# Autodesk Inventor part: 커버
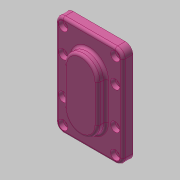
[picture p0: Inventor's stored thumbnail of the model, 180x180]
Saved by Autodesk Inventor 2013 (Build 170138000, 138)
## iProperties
Created: 2019-03
Part Number: 커버
Material: 알루미늄 6061
Document SubType Name: Modeling
Designer: mduedu
Density: 1 g/cm^3
Author: mduedu
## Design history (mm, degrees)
sketch "스케치1"
  geometry: L1 (-60, 40)-(60, 40); L2 (60, 40)-(60, -40); L3 (60, -40)-(-60, -40); L4 (-60, -40)-(-60, 40); L5 (-60, 40)-(60, -40); L6 (60, 40)-(-60, -40); 1 further point
  constraints: 12 end point, 2 midpoint, 2 parallel, 1 horizontal, 1 perpendicular
  dimensions: "d59" = 120 distance of L2.end L3.end; "d60" = 80 distance of L1.end L2.end
extrude "돌출1" new body sketch "스케치1" distance "d4" = 12; taper "d5" = 0 deg
sketch "스케치2"
  geometry: L1 (-20, -22)-(20, -22); L2 (20, -22)-(20, 22); L3 (20, 22)-(-20, 22); L4 (-20, 22)-(-20, -22); L5 (-20, -22)-(20, 22); L6 (20, -22)-(-20, 22); 3 further points
  constraints: 12 end point, 4 midpoint, 2 horizontal alignment, 2 parallel, 1 horizontal, 1 perpendicular, 4 other
  dimensions: "d6" = 40 distance between parallel lines of L2 L4; "d8" = 44 distance between parallel lines of L1 L3
extrude "돌출2" join sketch "스케치2" distance "d9" = 10; taper "d10" = 0 deg
fillet "모깎기1" dims "d11" = 9
fillet "모깎기2" dims "d12" = 3
sketch "스케치3"
  geometry: L1 (-31, -60)-(31, -60) reference; L2 (-40, 51)-(-40, -51) reference; L3 (31, 60)-(-31, 60) reference; L4 (40, -51)-(40, 51) reference; L5 (-17, -22)-(-17, 22) reference; L6 (17, 22)-(17, -22) reference; L7 (-31, 51)-(31, 51); L8 (31, 51)-(31, -51); L9 (31, -51)-(-31, -51); L10 (-31, -51)-(-31, 51); A1 r 9 centre (31, -51) between (31, -60) and (40, -51) reference; A2 r 9 centre (-31, -51) between (-40, -51) and (-31, -60) reference; A3 r 9 centre (-31, 51) between (-31, 60) and (-40, 51) reference; A4 r 9 centre (31, 51) between (40, 51) and (31, 60) reference; A5 r 17 centre (0, -22) between (-17, -22) and (17, -22) reference; A6 r 17 centre (0, 22) between (17, 22) and (-17, 22) reference; 9 further points
  constraints: 8 end point, 4 coincident, 4 horizontal alignment, 4 point on line, 2 parallel, 1 horizontal, 1 perpendicular
hole "구멍2" sketch "스케치3" at (-31, 51), (31, 51), (31, -51), (-31, -51), (-31, 22), (-31, -22), (31, 22), (31, -22) diameter "d28" = 5.5; stored, may be unused: countersink angle "d32" = 90 deg, drill point angle "d34" = 118 deg; dims "d29" = 6, "d30" = 4, "d31" = 2, "d33" = 8
sketch "스케치9"
  geometry: L1 (40, -51)-(40, 51) reference; L2 (31, 60)-(-31, 60) reference; L3 (-40, 51)-(-40, -51) reference; L4 (-31, -60)-(31, -60) reference; L5 (23, -22)-(23, 22) reference; L6 (-23, 22)-(-23, -22) reference; C1 r 2.75 at (31, 22) reference; C2 r 2.75 at (-31, 22) reference; C3 r 2.75 at (31, -51) reference; C4 r 2.75 at (-31, 51) reference; C5 r 2.75 at (31, 51) reference; C6 r 2.75 at (-31, -51) reference; C7 r 2.75 at (-31, -22) reference; C8 r 2.75 at (31, -22) reference; A1 r 9 centre (31, -51) between (31, -60) and (40, -51) reference; A2 r 9 centre (31, 51) between (40, 51) and (31, 60) reference; A3 r 9 centre (-31, 51) between (-31, 60) and (-40, 51) reference; A4 r 9 centre (-31, -51) between (-40, -51) and (-31, -60) reference; A5 r 23 centre (0, -22) between (-23, -22) and (23, -22) reference; A6 r 23 centre (0, 22) between (23, 22) and (-23, 22) reference; 9 further points
  constraints: 8 coincident
hole "구멍4" sketch "스케치9" at (-31, 51), (31, 51), (31, 22), (-31, 22), (-31, -22), (31, -22), (31, -51), (-31, -51) diameter "d69" = 11; stored, may be unused: countersink angle "d73" = 90 deg, drill point angle "d75" = 0 deg; dims "d70" = 6, "d71" = 4, "d72" = 2, "d74" = 5.4
fillet "모깎기3" dims "d68" = 3
sketch "스케치6"
  geometry: C1 r 12.5 at (0, 22); 1 further point
  constraints: 1 centre point, 1 vertical alignment
  dimensions: "d43" = 25 diameter of C1; "d45" = 22 distance of C1.centre point (0, 0)
extrude "돌출5" cut sketch "스케치6" distance "d47" = 15; taper "d48" = 0 deg
node "솔리드1"
mirror "대칭1"
node "투영된 루프2"
node "투영된 루프3"
node "투영된 루프4"
